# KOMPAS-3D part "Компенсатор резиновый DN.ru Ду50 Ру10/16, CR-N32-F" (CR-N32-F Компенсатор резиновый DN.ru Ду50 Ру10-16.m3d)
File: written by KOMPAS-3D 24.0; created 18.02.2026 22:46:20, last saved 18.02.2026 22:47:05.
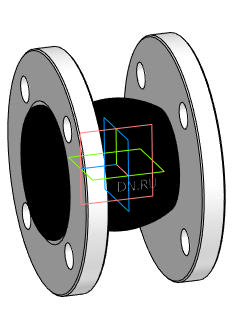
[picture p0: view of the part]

Document properties: Автор: DN.RU; Полное имя файла: D:\PROJECT CAD\DN.RU\...178(2)(ACTUALE). CR-N32-F Компенсатор резиновый DN.ru Ру10-16\CR-N32-F Компенсатор резиновый DN.ru Ру10-16\DN50\CR-N32-F Компенсатор резиновый DN.ru Ду50 Ру10-16 (2d).m3d

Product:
- Body: Твердое тело2  | qty 1
    Масса: 6.569601
- Part/product: Компенсатор резиновый DN.ru Ду50 Ру10/16  | designation CR-N32-F
    Масса: 5
    Раздел спецификации: Прочие изделия
    Комментарий: D140-02391
    Примечание: D140-02376
    additional columns: Типовые

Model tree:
1. Твердое тело2  (labels: Твердое тело2)

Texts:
  CR-N32-F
